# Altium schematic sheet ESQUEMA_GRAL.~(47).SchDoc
size A3; PageSetup: Record=PageOptions|CenterHorizontal=True|CenterVertical=True|PrintScale=0.71|XCorrection=1.00|YCorrection=1.00|PrintKind=1|BorderSize=5000000|LeftOffset=0|BottomOffset=0|Orientation=2|PaperLength=1000|PaperWidth=1000|Scale=100|PaperSource=15|PrintQuality=1200|MediaType=1|DitherType=10|PaperKind=A4|PrintScaleMode=1
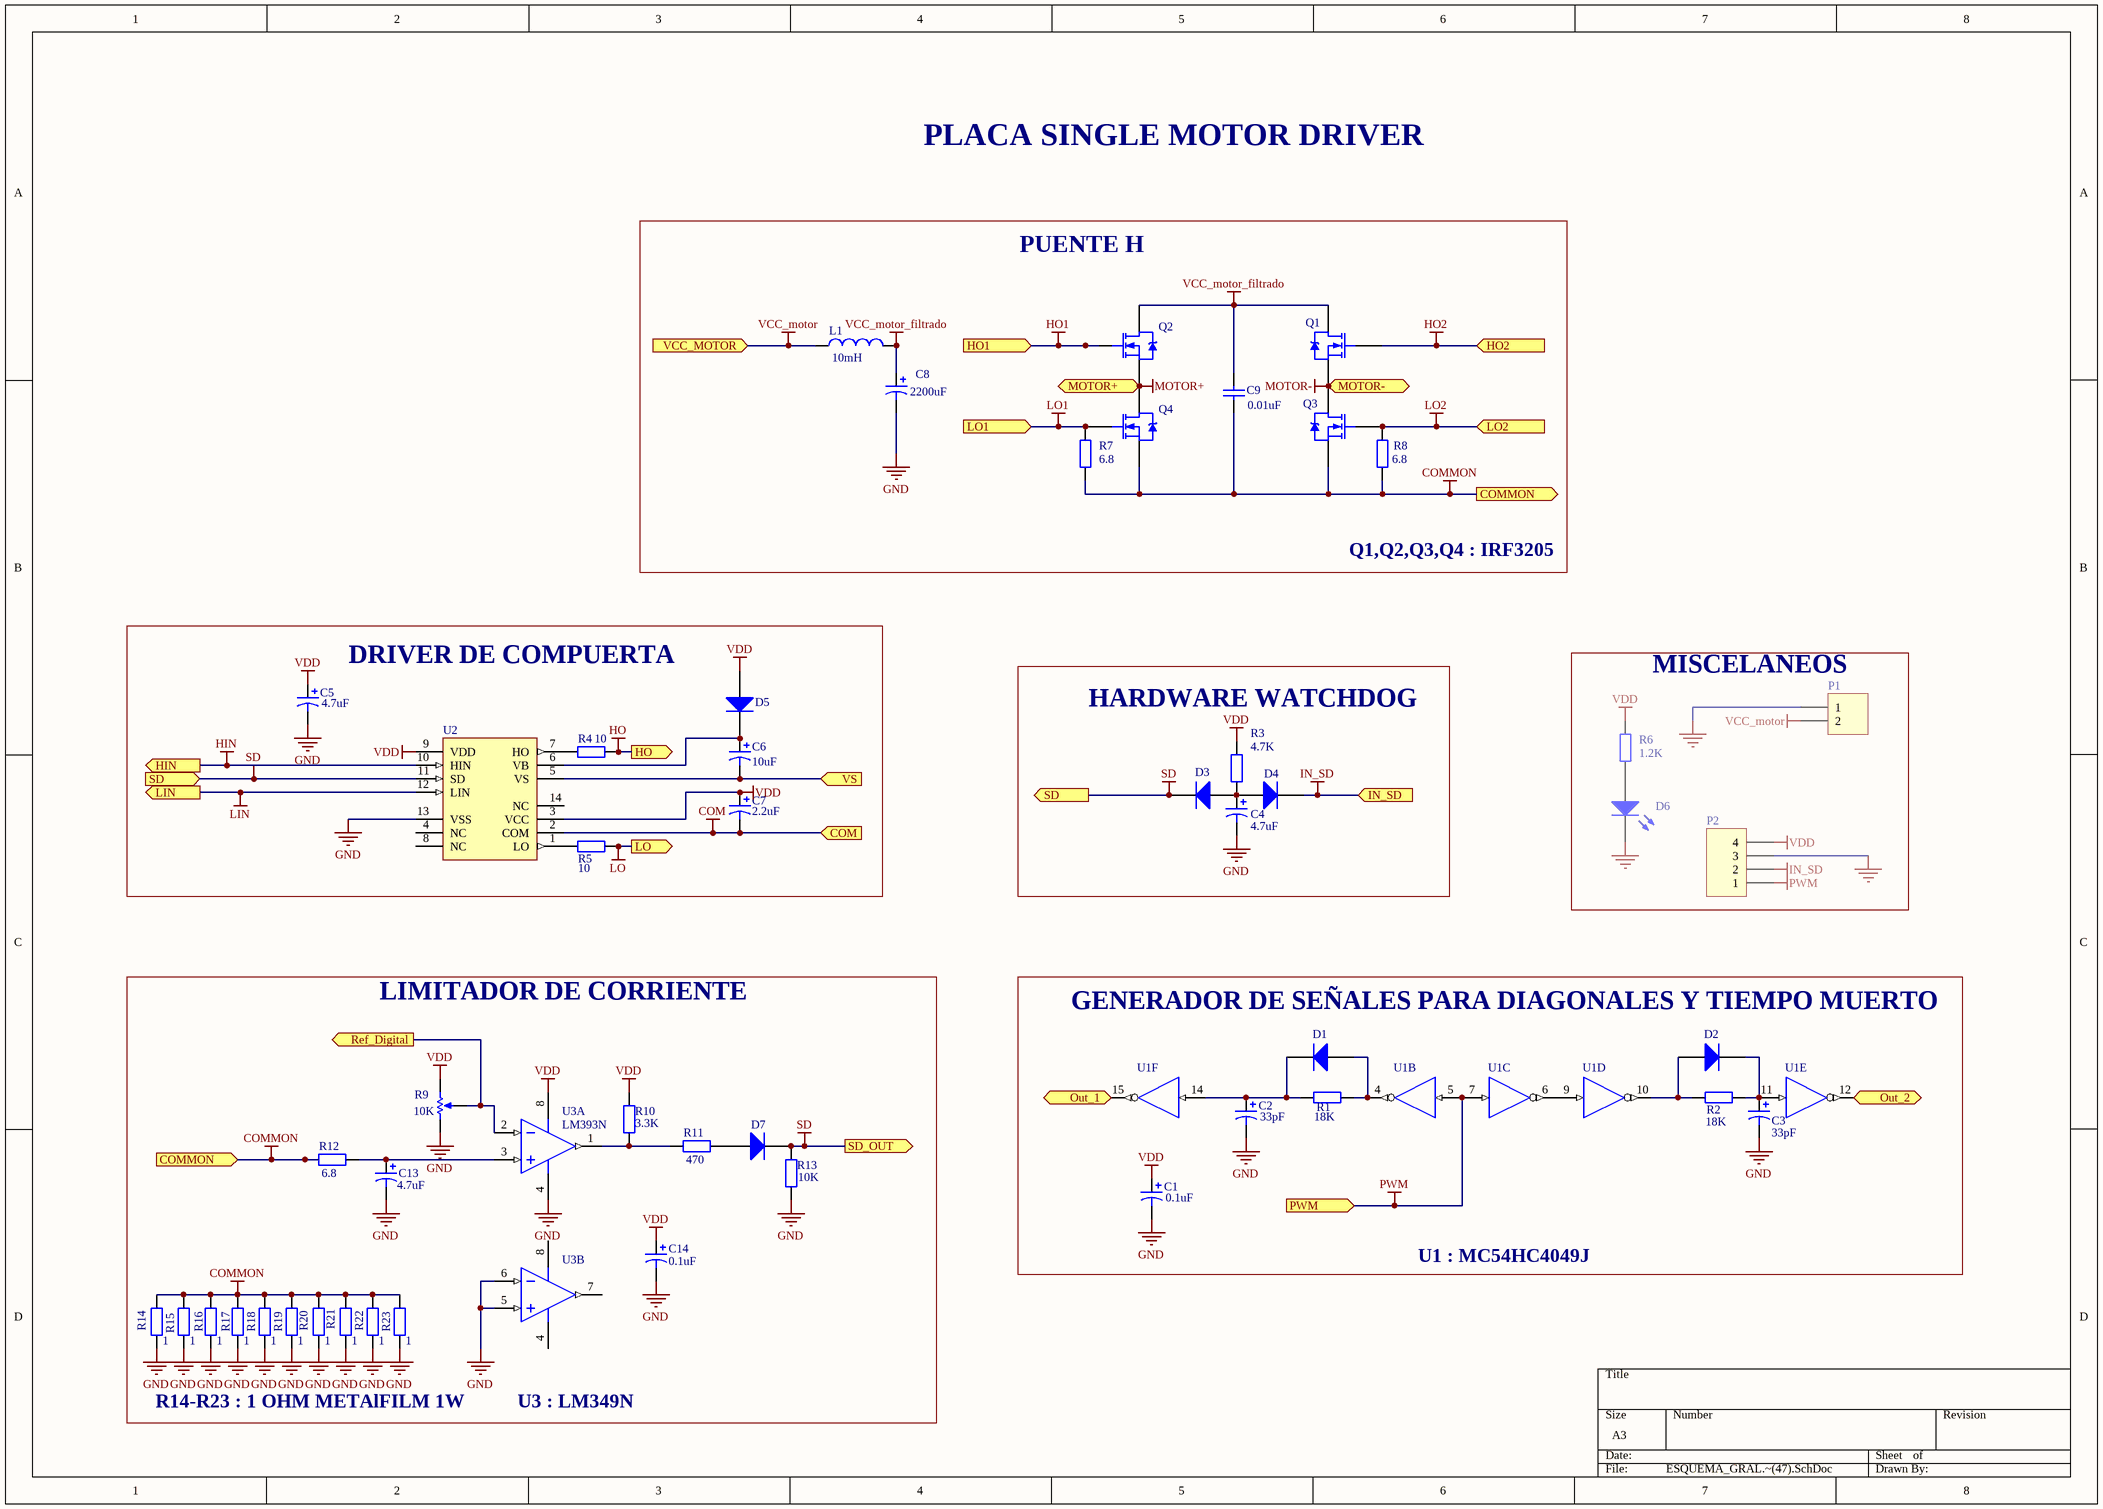
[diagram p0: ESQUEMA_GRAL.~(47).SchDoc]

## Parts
C1  value 0.1uF  [CAPPR2.5-6.3X5]  (hidden comment: Cap Pol1)
C2  value 33pF  [CAPPR2.5-6.3X5]  (hidden comment: Cap Pol1)
C3  value 33pF  [CAPPR2.5-6.3X5]  (hidden comment: Cap Pol1)
C4  value 4.7uF  [CAPPR2.5-6.3X5]  (hidden comment: Cap Pol1)
C5  value 4.7uF  [CAPPR2.5-6.3X5]  (hidden comment: Cap Pol1)
C6  value 10uF  [CAPPR2.5-6.3X5]  (hidden comment: Cap Pol1)
C7  value 2.2uF  [CAPPR2.5-6.3X5]  (hidden comment: Cap Pol1)
C8  value 2200uF  [CAPPR5-13X16]  (hidden comment: Cap Pol1)
C9  value 0.01uF  [RAD-0.2]  (hidden comment: Cap)
C13  value 4.7uF  [CAPPR2.5-6.3X5]  (hidden comment: Cap Pol1)
C14  value 0.1uF  [CAPPR2.5-6.3X5]  (hidden comment: Cap Pol1)
D1  Diode  [DO-204AL]  (value not drawn)
D2  Diode  [DO-204AL]  (value not drawn)
D3  Diode  [DO-204AL]  (value not drawn)
D4  Diode  [DO-204AL]  (value not drawn)
D5  Diode  [DO-204AL]  (value not drawn)
D6  LED0  [CAPPR2.5-6.3X5]  (value not drawn)
D7  Diode  [DO-204AL]  (value not drawn)
L1  value 10mH  [bobina_Choque]  (hidden comment: Inductor)
P1  Header 2  [pwheader1x2]  (value not drawn)
P2  Header 4  [HDR1X5]  (value not drawn)
Q1  IRF3205  [TO-220AB]  (value not drawn)
Q2  IRF3205  [TO-220AB]  (value not drawn)
Q3  IRF3205  [TO-220AB]  (value not drawn)
Q4  IRF3205  [TO-220AB]  (value not drawn)
R1  value 18K  [AXIAL-0.3]  (hidden comment: Res2)
R2  value 18K  [AXIAL-0.3]  (hidden comment: Res2)
R3  value 4.7K  [AXIAL-0.3]  (hidden comment: Res2)
R4  value 10  [AXIAL-0.3]  (hidden comment: Res2)
R5  value 10  [AXIAL-0.3]  (hidden comment: Res2)
R6  value 1.2K  [AXIAL-0.3]  (hidden comment: Res2)
R7  value 6.8  [AXIAL-0.3]  (hidden comment: Res2)
R8  value 6.8  [AXIAL-0.3]  (hidden comment: Res2)
R9  value 10K  [VR5]  (hidden comment: RPot)
R10  value 3.3K  [AXIAL-0.3]  (hidden comment: Res2)
R11  value 470  [AXIAL-0.3]  (hidden comment: Res2)
R12  value 6.8  [AXIAL-0.3]  (hidden comment: Res2)
R13  value 10K  [AXIAL-0.3]  (hidden comment: Res2)
R14  value 1  [AXIAL-0.4]  (hidden comment: Res2)
R15  value 1  [AXIAL-0.4]  (hidden comment: Res2)
R16  value 1  [AXIAL-0.4]  (hidden comment: Res2)
R17  value 1  [AXIAL-0.4]  (hidden comment: Res2)
R18  value 1  [AXIAL-0.4]  (hidden comment: Res2)
R19  value 1  [AXIAL-0.4]  (hidden comment: Res2)
R20  value 1  [AXIAL-0.4]  (hidden comment: Res2)
R21  value 1  [AXIAL-0.4]  (hidden comment: Res2)
R22  value 1  [AXIAL-0.4]  (hidden comment: Res2)
R23  value 1  [AXIAL-0.4]  (hidden comment: Res2)
U1  MC54HC4049J  [620-09]  (value not drawn)  (parts B,C,D,E,F of 6)
U2  IR2110  [PDIP14]  (value not drawn)
U3  LM393N  [626-05]  (parts A,B of 2)

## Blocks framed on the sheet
PUENTE H: C8 C9 L1 Q1-Q4 R7 R8
DRIVER DE COMPUERTA: C5-C7 D5 R4 R5 U2
HARDWARE WATCHDOG: C4 D3 D4 R3
MISCELANEOS: D6 P1 P2 R6
LIMITADOR DE CORRIENTE: C13 C14 D7 R9-R23 U3
GENERADOR DE SEÑALES PARA DIAGONALES Y TIEMPO MUERTO: C1-C3 D1 D2 R1 R2 U1

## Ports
COM (in), COMMON (in), COMMON (out), HIN (out), HO1 (in), HO2 (in), HO (out), IN_SD (in), LIN (out), LO1 (in), LO2 (in), LO (out), MOTOR+ (bidir), MOTOR- (bidir), Out_1 (out), Out_2 (out), PWM (in), Ref_Digital (out), SD (in), SD (out), SD_OUT (out), VCC_MOTOR (in), VS (in)

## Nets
COM: C7.2 U2.2(COM) ; port COM
COMMON: C9.1 Q3.3(S) Q4.3(S) R7.1 R8.1 R12.1 R14.2 R15.2 R16.2 R17.2 R18.2 R19.2 R20.2 R21.2 R22.2 R23.2 ; port COMMON
GND: C1.2 C2.2 C3.2 C4.2 C5.2 C8.2 C13.2 C14.2 D6.2(K) P1.1 P2.3 R9.1(TOP) R13.1 R14.1 R15.1 R16.1 R17.1 R18.1 R19.1 R20.1 R21.1 R22.1 R23.1 U1.8(GND) U2.13(VSS) U3.4(GND) U3.5(IN+) U3.6(IN-)
HIN: U2.10(HIN) ; port HIN
HO: R4.2 ; port HO
HO1: Q2.1(G) ; port HO1
HO2: Q1.1(G) ; port HO2
IN_SD: D4.2(K) P2.2 ; port IN_SD
LIN: U2.12(LIN) ; port LIN
LO: R5.2 ; port LO
LO1: Q4.1(G) R7.2 ; port LO1
LO2: Q3.1(G) R8.2 ; port LO2
MOTOR+: Q2.3(S) Q4.2(D) ; port MOTOR+
MOTOR-: Q1.3(S) Q3.2(D) ; port MOTOR-
PWM: P2.1 U1.5(A) U1.7(A) ; port PWM
SD: D3.2(K) D7.2(K) R13.2 U2.11(SD) ; port SD_OUT, port SD
VCC_motor: L1.1 P1.2 ; port VCC_MOTOR
VCC_motor_filtrado: C8.1 C9.2 L1.2 Q1.2(D) Q2.2(D)
VDD: C1.1 C5.1 C7.1 C14.1 D5.1(A) P2.4 R3.2 R6.2 R9.2(BOT) R10.2 U1.1(VDD) U2.3(VCC) U2.9(VDD) U3.8(V+)
Out_1: U1.15(Y) ; port Out_1
Out_2: U1.12(Y) ; port Out_2
Ref_Digital: R9.3(TAP) U3.2(IN-) ; port Ref_Digital
VS: C6.2 U2.5(VS) ; port VS
NetC2_1: C2.1 D1.2(K) R1.1 U1.14(A)
NetC3_1: C3.1 D2.2(K) R2.2 U1.11(A)
NetC4_1: C4.1 D3.1(A) D4.1(A) R3.1
NetC6_1: C6.1 D5.2(K) U2.6(VB)
NetC13_1: C13.1 R12.2 U3.3(IN+)
NetD1_1: D1.1(A) R1.2 U1.4(Y)
NetD2_1: D2.1(A) R2.1 U1.10(Y)
NetD6_1: D6.1(A) R6.1
NetD7_1: D7.1(A) R11.2
NetR4_1: R4.1 U2.7(HO)
NetR5_1: R5.1 U2.1(LO)
NetR10_1: R10.1 R11.1 U3.1(OUT)
NetU1_6: U1.6(Y) U1.9(A)

Not connected (* = marked no-connect by the designer): U2 4(NC) 8(NC) 14(NC); U3 7(OUT)

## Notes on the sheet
- PLACA SINGLE MOTOR DRIVER
- Q1,Q2,Q3,Q4 : IRF3205
- U1 : MC54HC4049J
- R14-R23 : 1 OHM METAlFILM 1W
- U3 : LM349N

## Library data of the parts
C1-C8 C14 = Cap Pol1: Polarized Capacitor (Radial)
C9 = Cap: Capacitor
C13 = Cap Pol1: Polarized 16V
D1 D2 = Diode: 1N4148
D3 D4 D7 = Diode: 1n4148
D5 = Diode: 1N5819
D6 = LED0: Typical INFRARED GaAs LED
L1 = Inductor: Code_IEC: 1005
P1 = Header 2: Header, 2-Pin
P2 = Header 4: Header, 4-Pin
Q1-Q4 = IRF3205: HEXFET Power MOSFET; Note: Pin 2 is electrically connected to pin 4.
R1-R8 = Res2: Resistor
R9 = RPot: Potenciomentro multivuelta; Sim Note: Enter the Resistance value and the set point into parameter fields.; Set Position: 0.5
R10-R13 = Res2: metal film 1/2 W
R14-R23 = Res2: metal film 1W
U1 = MC54HC4049J: Hex Inverting Buffer/Logic-Level Down Converter; Note: Pins 13 & 16 are NC and not drawn.
U2 = IR2110: High and Low Side Driver; Note: Pins 4, 8 and 14 are not connected
U3 = LM393N: Dual Comparator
